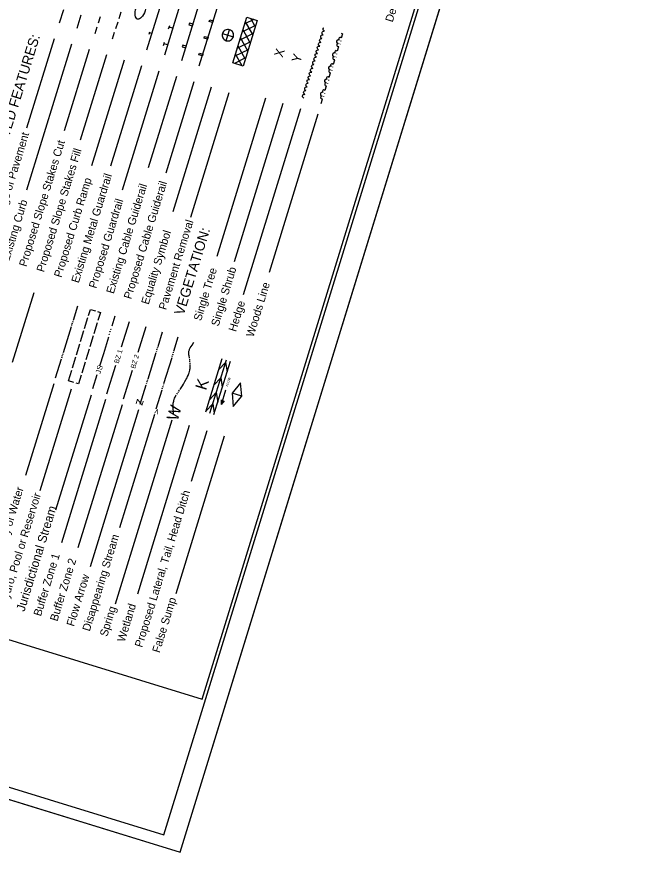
# Model space of a CAD drawing. Extents: x 1347947 to 1350662, y 1027710 to 1030532.
# Drawn here: x 1349987 to 1350662, y 1027875 to 1028788 of the extents above; entities that cross this region are included whole.
import ezdxf

# ---------------------------------------------------------------- set-up
doc = ezdxf.new("R2010")
doc.units = 0
doc.layers.add('Sheet Symbology CELL', color=7, linetype='Continuous')

msp = doc.modelspace()

# ---------------------------------------------------------------- linework, layer by layer
at = {"layer": 'Sheet Symbology CELL'}
for p, q in [((1350165.97, 1027874.54), (1350661.6, 1029483.96)), ((1350129.68, 1028751.93), (1350153.22, 1028828.39)), ((1350172.34, 1028822.5), (1350148.79, 1028746.04)), ((1350167.9, 1028740.16), (1350191.45, 1028816.61)), ((1350187.02, 1028734.27), (1350210.56, 1028810.73)), ((1350034.27, 1028781.48), (1350038.68, 1028795.81)), ((1350053.38, 1028775.59), (1350057.8, 1028789.93)), ((1350078.63, 1028788.01), (1350076.41, 1028780.79)), ((1350101.13, 1028793.11), (1350098.89, 1028785.85)), ((1350223.75, 1028737.56), (1350239.08, 1028787.35)), ((1350246.68, 1028785.01), (1350236.89, 1028780.23)), ((1350239.08, 1028787.35), (1350250.27, 1028783.91)), ((1350248.25, 1028777.36), (1350243.29, 1028786.05)), ((1350072.95, 1028769.56), (1350075.19, 1028776.83)), ((1350097.74, 1028782.12), (1350095.52, 1028774.91)), ((1350153.47, 1028774.66), (1350154.65, 1028778.48)), ((1350157.83, 1028775.41), (1350154.06, 1028776.57)), ((1350248.59, 1028778.46), (1350234.15, 1028771.34)), ((1350250.27, 1028783.91), (1350234.93, 1028734.11)), ((1350245.53, 1028768.52), (1350237.57, 1028782.43)), ((1350322.28, 1028774.44), (1350322.56, 1028775.35)), ((1350322.56, 1028775.35), (1350323.27, 1028775.97)), ((1350323.27, 1028775.97), (1350323.33, 1028776)), ((1350092.06, 1028763.68), (1350094.3, 1028770.94)), ((1350132.33, 1028769.04), (1350133.07, 1028771.43)), ((1350135.09, 1028769.5), (1350132.7, 1028770.24)), ((1350212.31, 1028769.62), (1350218.28, 1028767.78)), ((1350216.44, 1028761.81), (1350218.28, 1028767.78)), ((1350218.28, 1028767.78), (1350220.12, 1028773.75)), ((1350218.28, 1028767.78), (1350224.25, 1028765.94)), ((1350245.85, 1028769.57), (1350231.43, 1028762.5)), ((1350242.79, 1028759.63), (1350234.85, 1028773.59)), ((1350319.78, 1028766.32), (1350320.05, 1028767.23)), ((1350319.97, 1028765.42), (1350319.78, 1028766.32)), ((1350320.05, 1028767.23), (1350320.77, 1028767.84)), ((1350320.77, 1028767.84), (1350321.55, 1028768.18)), ((1350321.03, 1028770.38), (1350321.31, 1028771.29)), ((1350321.22, 1028769.48), (1350321.03, 1028770.38)), ((1350321.67, 1028768.72), (1350321.22, 1028769.48)), ((1350321.31, 1028771.29), (1350322.02, 1028771.91)), ((1350321.55, 1028768.18), (1350322.42, 1028768.12)), ((1350322.49, 1028768.15), (1350321.67, 1028768.72)), ((1350322.02, 1028771.91), (1350322.8, 1028772.24)), ((1350322.47, 1028773.55), (1350322.28, 1028774.44)), ((1350322.92, 1028772.78), (1350322.47, 1028773.55)), ((1350322.8, 1028772.24), (1350323.67, 1028772.18)), ((1350323.74, 1028772.21), (1350322.92, 1028772.78)), ((1350342.41, 1028764.89), (1350343.88, 1028769.67)), ((1350028.26, 1028763.94), (1349998.14, 1028666.12)), ((1350047.38, 1028758.05), (1349998.18, 1028598.3)), ((1350147.88, 1028756.5), (1350149.06, 1028760.32)), ((1350152.24, 1028757.25), (1350148.47, 1028758.41)), ((1350243.11, 1028760.68), (1350228.71, 1028753.66)), ((1350240.05, 1028750.74), (1350232.12, 1028764.75)), ((1350317.27, 1028758.2), (1350317.55, 1028759.1)), ((1350317.47, 1028757.3), (1350317.27, 1028758.2)), ((1350317.91, 1028756.53), (1350317.47, 1028757.3)), ((1350317.55, 1028759.1), (1350318.27, 1028759.72)), ((1350318.27, 1028759.72), (1350319.05, 1028760.05)), ((1350318.52, 1028762.26), (1350318.8, 1028763.16)), ((1350318.72, 1028761.36), (1350318.52, 1028762.26)), ((1350319.16, 1028760.6), (1350318.72, 1028761.36)), ((1350318.8, 1028763.16), (1350319.52, 1028763.78)), ((1350319.05, 1028760.05), (1350319.92, 1028760)), ((1350319.98, 1028760.03), (1350319.16, 1028760.6)), ((1350319.52, 1028763.78), (1350320.3, 1028764.12)), ((1350320.41, 1028764.66), (1350319.97, 1028765.42)), ((1350320.3, 1028764.12), (1350321.17, 1028764.06)), ((1350321.23, 1028764.09), (1350320.41, 1028764.66)), ((1350340.81, 1028758.01), (1350340.96, 1028758.49)), ((1350341.84, 1028761.35), (1350341.99, 1028761.83)), ((1350066.49, 1028752.16), (1350039.06, 1028663.1)), ((1350240.39, 1028751.84), (1350225.97, 1028744.77)), ((1350237.33, 1028741.9), (1350229.39, 1028755.86)), ((1350314.51, 1028747.54), (1350315.3, 1028747.87)), ((1350314.77, 1028750.07), (1350315.05, 1028750.98)), ((1350314.97, 1028749.17), (1350314.77, 1028750.07)), ((1350315.41, 1028748.41), (1350314.97, 1028749.17)), ((1350315.05, 1028750.98), (1350315.76, 1028751.6)), ((1350315.3, 1028747.87), (1350316.17, 1028747.81)), ((1350316.23, 1028747.84), (1350315.41, 1028748.41)), ((1350315.76, 1028751.6), (1350316.55, 1028751.93)), ((1350316.02, 1028754.13), (1350316.3, 1028755.04)), ((1350316.22, 1028753.24), (1350316.02, 1028754.13)), ((1350316.66, 1028752.47), (1350316.22, 1028753.24)), ((1350316.3, 1028755.04), (1350317.02, 1028755.66)), ((1350316.55, 1028751.93), (1350317.42, 1028751.87)), ((1350317.48, 1028751.91), (1350316.66, 1028752.47)), ((1350317.02, 1028755.66), (1350317.8, 1028755.99)), ((1350317.8, 1028755.99), (1350318.67, 1028755.93)), ((1350318.73, 1028755.97), (1350317.91, 1028756.53)), ((1350337.99, 1028750.56), (1350339.47, 1028755.34)), ((1350085.61, 1028746.28), (1350056.84, 1028652.87)), ((1350104.72, 1028740.39), (1350069.13, 1028624.82)), ((1350237.65, 1028742.95), (1350225.47, 1028737.03)), ((1350233.83, 1028734.45), (1350226.65, 1028746.97)), ((1350311.02, 1028737.89), (1350311.3, 1028738.79)), ((1350311.3, 1028738.79), (1350312.01, 1028739.41)), ((1350312.01, 1028739.41), (1350312.8, 1028739.75)), ((1350312.27, 1028741.95), (1350312.55, 1028742.86)), ((1350312.46, 1028741.05), (1350312.27, 1028741.95)), ((1350312.91, 1028740.29), (1350312.46, 1028741.05)), ((1350312.55, 1028742.86), (1350313.26, 1028743.47)), ((1350312.8, 1028739.75), (1350313.67, 1028739.69)), ((1350313.73, 1028739.72), (1350312.91, 1028740.29)), ((1350313.26, 1028743.47), (1350314.05, 1028743.81)), ((1350313.52, 1028746.01), (1350313.8, 1028746.92)), ((1350313.72, 1028745.11), (1350313.52, 1028746.01)), ((1350314.16, 1028744.35), (1350313.72, 1028745.11)), ((1350313.8, 1028746.92), (1350314.51, 1028747.54)), ((1350314.05, 1028743.81), (1350314.92, 1028743.75)), ((1350314.98, 1028743.78), (1350314.16, 1028744.35)), ((1350333.58, 1028736.22), (1350335.05, 1028741)), ((1350336.4, 1028743.67), (1350336.54, 1028744.15)), ((1350337.43, 1028747.02), (1350337.57, 1028747.5)), ((1350123.67, 1028734.39), (1350089.87, 1028624.64)), ((1350234.93, 1028734.11), (1350223.75, 1028737.56)), ((1350224.32, 1028737.38), (1350223.91, 1028738.08)), ((1350308.52, 1028729.76), (1350308.8, 1028730.67)), ((1350308.71, 1028728.87), (1350308.52, 1028729.76)), ((1350308.8, 1028730.67), (1350309.51, 1028731.29)), ((1350309.51, 1028731.29), (1350310.29, 1028731.62)), ((1350309.77, 1028733.82), (1350310.05, 1028734.73)), ((1350309.96, 1028732.93), (1350309.77, 1028733.82)), ((1350310.41, 1028732.16), (1350309.96, 1028732.93)), ((1350310.05, 1028734.73), (1350310.76, 1028735.35)), ((1350310.29, 1028731.62), (1350311.16, 1028731.56)), ((1350311.23, 1028731.6), (1350310.41, 1028732.16)), ((1350310.76, 1028735.35), (1350311.54, 1028735.68)), ((1350311.21, 1028736.99), (1350311.02, 1028737.89)), ((1350311.66, 1028736.22), (1350311.21, 1028736.99)), ((1350311.54, 1028735.68), (1350312.42, 1028735.63)), ((1350312.48, 1028735.66), (1350311.66, 1028736.22)), ((1350331.98, 1028729.34), (1350332.13, 1028729.82)), ((1350333.01, 1028732.68), (1350333.16, 1028733.16)), ((1350142.79, 1028728.5), (1350102.69, 1028598.3)), ((1350161.9, 1028722.62), (1350131.2, 1028622.94)), ((1350306.02, 1028721.64), (1350306.3, 1028722.55)), ((1350306.21, 1028720.74), (1350306.02, 1028721.64)), ((1350306.66, 1028719.98), (1350306.21, 1028720.74)), ((1350306.3, 1028722.55), (1350307.01, 1028723.16)), ((1350307.01, 1028723.16), (1350307.79, 1028723.5)), ((1350307.27, 1028725.7), (1350307.55, 1028726.61)), ((1350307.46, 1028724.8), (1350307.27, 1028725.7)), ((1350307.91, 1028724.04), (1350307.46, 1028724.8)), ((1350307.55, 1028726.61), (1350308.26, 1028727.23)), ((1350307.79, 1028723.5), (1350308.66, 1028723.44)), ((1350308.73, 1028723.47), (1350307.91, 1028724.04)), ((1350308.26, 1028727.23), (1350309.04, 1028727.56)), ((1350309.16, 1028728.1), (1350308.71, 1028728.87)), ((1350309.04, 1028727.56), (1350309.91, 1028727.5)), ((1350309.98, 1028727.53), (1350309.16, 1028728.1)), ((1350329.16, 1028721.89), (1350330.64, 1028726.67)), ((1350181.02, 1028716.73), (1350150.32, 1028617.05)), ((1350303.26, 1028710.98), (1350304.04, 1028711.31)), ((1350303.51, 1028713.52), (1350303.79, 1028714.42)), ((1350303.71, 1028712.62), (1350303.51, 1028713.52)), ((1350304.15, 1028711.85), (1350303.71, 1028712.62)), ((1350303.79, 1028714.42), (1350304.51, 1028715.04)), ((1350304.04, 1028711.31), (1350304.91, 1028711.25)), ((1350304.97, 1028711.29), (1350304.15, 1028711.85)), ((1350304.51, 1028715.04), (1350305.29, 1028715.38)), ((1350304.77, 1028717.58), (1350305.04, 1028718.49)), ((1350304.96, 1028716.68), (1350304.77, 1028717.58)), ((1350305.4, 1028715.92), (1350304.96, 1028716.68)), ((1350305.04, 1028718.49), (1350305.76, 1028719.1)), ((1350305.29, 1028715.38), (1350306.16, 1028715.32)), ((1350306.22, 1028715.35), (1350305.4, 1028715.92)), ((1350305.76, 1028719.1), (1350306.54, 1028719.44)), ((1350306.54, 1028719.44), (1350307.41, 1028719.38)), ((1350307.47, 1028719.41), (1350306.66, 1028719.98)), ((1350324.75, 1028707.55), (1350326.22, 1028712.33)), ((1350327.57, 1028715), (1350327.71, 1028715.48)), ((1350328.6, 1028718.35), (1350328.74, 1028718.83)), ((1350200.13, 1028710.85), (1350158.15, 1028574.54)), ((1350219.24, 1028704.96), (1350177.27, 1028568.65)), ((1350299.76, 1028701.33), (1350300.04, 1028702.24)), ((1350300.04, 1028702.24), (1350300.75, 1028702.86)), ((1350300.75, 1028702.86), (1350301.54, 1028703.19)), ((1350301.01, 1028705.39), (1350301.29, 1028706.3)), ((1350301.21, 1028704.5), (1350301.01, 1028705.39)), ((1350301.65, 1028703.73), (1350301.21, 1028704.5)), ((1350301.29, 1028706.3), (1350302.01, 1028706.92)), ((1350301.54, 1028703.19), (1350302.41, 1028703.13)), ((1350302.47, 1028703.16), (1350301.65, 1028703.73)), ((1350302.01, 1028706.92), (1350302.79, 1028707.25)), ((1350302.26, 1028709.45), (1350302.54, 1028710.36)), ((1350302.46, 1028708.56), (1350302.26, 1028709.45)), ((1350302.9, 1028707.79), (1350302.46, 1028708.56)), ((1350302.54, 1028710.36), (1350303.26, 1028710.98)), ((1350302.79, 1028707.25), (1350303.66, 1028707.19)), ((1350303.72, 1028707.23), (1350302.9, 1028707.79)), ((1350324.18, 1028704.01), (1350324.33, 1028704.49)), ((1350259.35, 1028699.03), (1350206.04, 1028525.93)), ((1350278.46, 1028693.15), (1350225.15, 1028520.04)), ((1350299.96, 1028700.43), (1350299.76, 1028701.33)), ((1350300.4, 1028699.67), (1350299.96, 1028700.43)), ((1350301.22, 1028699.1), (1350300.4, 1028699.67)), ((1350320.33, 1028693.22), (1350321.81, 1028697.99)), ((1350323.15, 1028700.67), (1350323.3, 1028701.14)), ((1350297.57, 1028687.26), (1350234.98, 1028483.99)), ((1350316.69, 1028681.37), (1350263.38, 1028508.27)), ((1349982.76, 1028410.18), (1350006.3, 1028486.64)), ((1350049.24, 1028456.18), (1350054.09, 1028471.92)), ((1350061.56, 1028447.19), (1350065.24, 1028459.13)), ((1350038.35, 1028420.81), (1350047.18, 1028449.49)), ((1350047.47, 1028450.44), (1350047.77, 1028451.4)), ((1350048.06, 1028452.35), (1350048.36, 1028453.31)), ((1350048.65, 1028454.26), (1350048.94, 1028455.22)), ((1350075.32, 1028453.39), (1350071.64, 1028441.44)), ((1350110.26, 1028454.62), (1350101.64, 1028426.61)), ((1350128.4, 1028449.04), (1350119.78, 1028421.03)), ((1350057.15, 1028432.85), (1350060.83, 1028444.8)), ((1350070.91, 1028439.05), (1350067.23, 1028427.11)), ((1350141.9, 1028427.64), (1350146.75, 1028443.39)), ((1350159.21, 1028422.31), (1350164.06, 1028438.05)), ((1350052.73, 1028418.52), (1350056.41, 1028430.46)), ((1350037.76, 1028418.9), (1350038.05, 1028419.86)), ((1350066.49, 1028424.72), (1350062.81, 1028412.77)), ((1350131.01, 1028392.28), (1350139.84, 1028420.95)), ((1350140.13, 1028421.91), (1350140.43, 1028422.86)), ((1350140.72, 1028423.82), (1350141.01, 1028424.77)), ((1350141.31, 1028425.73), (1350141.6, 1028426.69)), ((1350158.04, 1028418.49), (1350158.33, 1028419.44)), ((1350158.62, 1028420.4), (1350158.92, 1028421.35)), ((1350029.81, 1028393.08), (1350036.29, 1028414.12)), ((1350036.58, 1028415.08), (1350036.88, 1028416.04)), ((1350037.17, 1028416.99), (1350037.47, 1028417.95)), ((1350048.32, 1028404.18), (1350052, 1028416.13)), ((1350062.08, 1028410.38), (1350058.4, 1028398.43)), ((1350148.32, 1028386.95), (1350157.15, 1028415.62)), ((1350157.45, 1028416.57), (1350157.74, 1028417.53)), ((1350176.8, 1028410.67), (1350176.7, 1028411.65)), ((1350194.01, 1028356.08), (1350211.97, 1028414.39)), ((1350198.52, 1028354.42), (1350216.56, 1028412.98)), ((1350203.04, 1028353.3), (1350221, 1028411.61)), ((1350208.23, 1028402.24), (1350215.64, 1028410.01)), ((1350215.64, 1028410.01), (1350217.34, 1028399.71)), ((1350043.9, 1028389.85), (1350047.58, 1028401.79)), ((1350085.98, 1028375.78), (1350095.63, 1028407.12)), ((1350104.12, 1028370.19), (1350113.77, 1028401.53)), ((1350176.96, 1028408.67), (1350176.87, 1028409.66)), ((1350203.01, 1028385.29), (1350210.49, 1028393.27)), ((1350210.49, 1028393.27), (1350212.14, 1028382.85)), ((1350027.89, 1028386.85), (1349996.99, 1028286.5)), ((1350049.93, 1028387.99), (1350043.9, 1028389.85)), ((1350122.47, 1028364.54), (1350128.95, 1028385.59)), ((1350129.24, 1028386.55), (1350129.54, 1028387.5)), ((1350129.83, 1028388.46), (1350130.12, 1028389.41)), ((1350130.42, 1028390.37), (1350130.71, 1028391.32)), ((1350147.15, 1028383.12), (1350147.44, 1028384.08)), ((1350147.73, 1028385.04), (1350148.03, 1028385.99)), ((1350232.15, 1028387.63), (1350222.95, 1028376.53)), ((1350233.51, 1028373.28), (1350232.15, 1028387.63)), ((1350047, 1028380.97), (1350012.75, 1028269.73)), ((1350068.6, 1028374.31), (1350029.87, 1028248.54)), ((1350139.78, 1028359.21), (1350146.26, 1028380.26)), ((1350146.56, 1028381.21), (1350146.85, 1028382.17)), ((1350164.69, 1028378.76), (1350165.28, 1028379.57)), ((1350198.02, 1028369.09), (1350205.49, 1028377.03)), ((1350205.49, 1028377.03), (1350207.14, 1028366.61)), ((1350211.1, 1028364.16), (1350216, 1028380.08)), ((1350233.51, 1028373.28), (1350222.95, 1028376.53)), ((1350222.95, 1028376.53), (1350224, 1028362.01)), ((1350224, 1028362.01), (1350233.51, 1028373.28)), ((1350084.48, 1028369.42), (1350036.28, 1028212.92)), ((1350194.28, 1028356.94), (1350201.75, 1028364.88)), ((1350201.75, 1028364.88), (1350203.39, 1028354.42)), ((1350211.1, 1028364.16), (1350211.22, 1028369.15)), ((1350211.1, 1028364.16), (1350214.37, 1028368.18)), ((1350102.51, 1028363.87), (1350054.32, 1028207.37)), ((1350120.55, 1028358.32), (1350067.62, 1028186.44)), ((1350156.98, 1028347.1), (1350095.03, 1028145.95)), ((1350137.86, 1028352.98), (1350099.75, 1028229.21)), ((1350176.09, 1028341.21), (1350119.23, 1028156.56)), ((1350214.32, 1028329.44), (1350161.26, 1028157.15)), ((1350195.21, 1028335.33), (1350178.08, 1028279.73)), ((1349114.69, 1028198.29), (1350165.97, 1027874.54))]:
    msp.add_line(p, q, dxfattribs=at)
for points in [[(1350165.97, 1027874.54), (1350661.6, 1029483.96), (1349610.32, 1029807.71), (1349114.69, 1028198.29)], [(1350148.34, 1027893.58), (1350638.82, 1029486.26), (1349630.46, 1029796.8), (1349139.98, 1028204.11)], [(1349629.21, 1029784.1), (1349187.74, 1028350.54), (1350190.26, 1028041.81), (1350631.74, 1029475.37)], [(1350197.75, 1028782.72), (1350198.34, 1028784.63), (1350202.17, 1028783.45), (1350201.58, 1028781.54)], [(1350179.52, 1028777.88), (1350180.11, 1028779.8), (1350176.29, 1028780.97), (1350175.7, 1028779.06)], [(1350192.16, 1028764.56), (1350192.75, 1028766.47), (1350196.57, 1028765.3), (1350195.98, 1028763.38)], [(1350172.17, 1028753.99), (1350172.75, 1028755.9), (1350168.93, 1028757.08), (1350168.34, 1028755.17)], [(1350186.57, 1028746.4), (1350187.16, 1028748.32), (1350190.98, 1028747.14), (1350190.39, 1028745.23)]]:
    msp.add_lwpolyline(points, close=True, dxfattribs=at)
for points in [[(1350065.98, 1028461.52), (1350067.99, 1028468.05), (1350073.41, 1028466.38)], [(1350075.8, 1028465.64), (1350078.81, 1028464.71), (1350076.06, 1028455.78)], [(1350091.73, 1028450.1), (1350095.09, 1028461.01)], [(1350082.43, 1028419.91), (1350088.02, 1028438.06)], [(1350176.31, 1028414.64), (1350176.22, 1028415.16), (1350175.82, 1028417.34), (1350175.65, 1028418.44), (1350175.55, 1028419.55), (1350175.53, 1028420.38), (1350175.57, 1028421.1), (1350175.63, 1028421.74), (1350175.71, 1028422.29), (1350175.94, 1028423.24), (1350176.15, 1028423.93), (1350176.35, 1028424.43), (1350176.69, 1028425.17), (1350177.09, 1028425.87), (1350179.07, 1028428.97), (1350181.05, 1028432.06)], [(1350078.31, 1028406.5), (1350082.43, 1028419.91)], [(1350176.6, 1028412.65), (1350176.58, 1028412.87), (1350176.48, 1028413.64)], [(1350165.87, 1028380.38), (1350166.34, 1028381.03), (1350167.15, 1028382.25), (1350168.62, 1028384.61), (1350169.71, 1028386.39), (1350171.27, 1028389.09), (1350172.78, 1028391.83), (1350173.57, 1028393.36), (1350174.22, 1028394.73), (1350174.76, 1028395.95), (1350175.19, 1028397.04), (1350175.54, 1028397.99), (1350175.83, 1028398.84), (1350176.26, 1028400.33), (1350176.53, 1028401.46), (1350176.69, 1028402.33), (1350176.89, 1028403.61), (1350177.01, 1028404.91), (1350177.04, 1028405.91), (1350177.05, 1028406.78), (1350177.01, 1028407.67)], [(1350057.66, 1028396.05), (1350054.73, 1028386.51), (1350052.31, 1028387.26)], [(1350070.64, 1028381.61), (1350075.35, 1028396.91)], [(1350158.9, 1028353.33), (1350158.6, 1028356.4), (1350158.29, 1028359.47), (1350158.24, 1028360.23), (1350158.19, 1028361.57), (1350158.23, 1028362.58), (1350158.33, 1028364.08), (1350158.52, 1028365.56), (1350158.74, 1028366.79), (1350158.98, 1028367.87), (1350159.24, 1028368.79), (1350159.49, 1028369.61), (1350160.01, 1028371), (1350160.44, 1028372.03), (1350160.81, 1028372.78), (1350161.4, 1028373.9), (1350161.84, 1028374.65)], [(1350162.38, 1028375.5), (1350162.64, 1028375.91), (1350162.93, 1028376.33)], [(1350163.51, 1028377.14), (1350163.76, 1028377.5), (1350164.1, 1028377.96)]]:
    msp.add_lwpolyline(points, dxfattribs=at)
for centre, radius, start, end in [((1350218.28, 1028767.78), 6.25, 162.8778, 252.88234), ((1350218.28, 1028767.78), 6.25, 72.8778, 162.88234), ((1350218.28, 1028767.78), 6.25, 342.8778, 72.88234), ((1350343.34, 1028771.35), 1.58, 229.13443, 276.6324), ((1350218.28, 1028767.78), 6.25, 252.8778, 342.88234), ((1350339, 1028760.66), 2.06, 58.84717, 266.91966), ((1350338.92, 1028757.02), 1.58, 91.31837, 292.11494), ((1350340.98, 1028763.71), 1.58, 33.6519, 234.44847), ((1350334.58, 1028746.32), 2.06, 58.84717, 266.91966), ((1350336.57, 1028749.37), 1.58, 33.6519, 234.44847), ((1350334.51, 1028742.68), 1.58, 91.31837, 292.11494), ((1350330.17, 1028731.99), 2.06, 58.84717, 266.91966), ((1350330.09, 1028728.35), 1.58, 91.31837, 292.11494), ((1350332.15, 1028735.04), 1.58, 33.6519, 234.44847), ((1350327.74, 1028720.7), 1.58, 33.6519, 234.44847), ((1350325.75, 1028717.65), 2.06, 58.84717, 266.91966), ((1350325.68, 1028714.01), 1.58, 91.31837, 292.11494), ((1350321.34, 1028703.32), 2.06, 58.84717, 266.91966), ((1350323.32, 1028706.37), 1.58, 33.6519, 234.44847), ((1350321.26, 1028699.68), 1.58, 91.31837, 292.11494)]:
    msp.add_arc(centre, radius, start, end, dxfattribs=at)
for centre, major_axis, ratio in [((1350122.76, 1028796.04), (3.3, 10.72), 0.462467), ((1350090.25, 1028446.25), (-0.188, 0.058), 0.938496), ((1350088.62, 1028440.95), (-0.188, 0.058), 0.938496), ((1350089.49, 1028443.78), (-0.188, 0.058), 0.938496)]:
    msp.add_ellipse(centre, major_axis=major_axis, ratio=ratio, dxfattribs=at)

# ---------------------------------------------------------------- texts
for s, height, rotation, p in [('Designated U/G Fiber Optics Cable (S.U.E.*)', 8.75, 72.88342, (1350398.39, 1028781.41)), ('ROADS AND RELATED FEATURES:', 11, 72.88342, (1349940.58, 1028531.71)), ('X', 10, 72.88342, (1350278.07, 1028742.85)), ('Y', 10, 72.88342, (1350297.19, 1028736.97)), ('Existing Edge of Pavement', 8.75, 72.88342, (1349959.69, 1028525.82)), ('Proposed Slope Stakes Cut', 8.75, 72.88342, (1349997.92, 1028514.05)), ('Proposed Slope Stakes Fill', 8.75, 72.88342, (1350017.04, 1028508.16)), ('Proposed Curb Ramp', 8.75, 72.88342, (1350036.15, 1028502.28)), ('Existing Metal Guardrail', 8.75, 72.88342, (1350055.1, 1028496.27)), ('Existing Cable Guiderail', 8.75, 72.88342, (1350093.32, 1028484.52)), ('Proposed Cable Guiderail', 8.75, 72.88342, (1350112.44, 1028478.63)), ('Existing Curb', 8.75, 72.88342, (1349978.81, 1028519.93)), ('Proposed Guardrail', 8.75, 72.88342, (1350074.21, 1028490.4)), ('Pavement Removal', 8.75, 72.88342, (1350150.67, 1028466.86)), ('VEGETATION:', 11, 72.88342, (1350169.86, 1028460.94)), ('Equality Symbol', 8.75, 72.88342, (1350131.55, 1028472.75)), ('Single Tree', 8.75, 72.88342, (1350188.87, 1028454.79)), ('Single Shrub', 8.75, 72.88342, (1350207.98, 1028448.91)), ('Woods Line', 8.75, 72.88342, (1350246.21, 1028437.14)), ('Hedge', 8.75, 72.88342, (1350227.09, 1028443.02)), ('BZ 1', 5.315, 72.88342, (1350098.66, 1028408.43)), ('BZ 2', 5.315, 72.88342, (1350116.73, 1028402.87)), ('JS', 5.906, 72.88342, (1350078.86, 1028396.99)), ('K', 12.75, 72.88342, (1350194.37, 1028378.9)), ('FLOW', 2.593, 72.88342, (1350218.45, 1028383.44)), ('z', 10, 252.88344, (1350119.16, 1028370.8)), ('W', 12.75, 72.88342, (1350163.11, 1028345.36)), ('v', 6.6, 162.64256, (1350143.35, 1028358.11)), ('Stream or Body of Water', 8.75, 72.88342, (1349957.14, 1028149.42)), ('Hydro, Pool or Reservoir', 8.75, 72.88342, (1349976.25, 1028143.53)), ('Proposed Lateral, Tail, Head Ditch', 8.75, 72.88342, (1350124.45, 1028097.89)), ('Jurisdictional Stream', 9.646, 72.88342, (1349995.78, 1028137.17)), ('Disappearing Stream', 8.75, 72.88342, (1350067.11, 1028115.55)), ('Buffer Zone 1', 8.75, 72.88342, (1350013.73, 1028131.99)), ('Buffer Zone 2', 8.75, 72.88342, (1350031.76, 1028126.44)), ('Flow Arrow', 8.75, 72.88342, (1350049.8, 1028120.89)), ('Wetland', 8.75, 72.88342, (1350105.34, 1028103.78)), ('False Sump', 8.75, 72.88342, (1350143.57, 1028092.01)), ('Spring', 8.75, 72.88342, (1350086.23, 1028109.67))]:
    msp.add_text(s, height=height, rotation=rotation, dxfattribs=at).set_placement(p)

doc.saveas('drawing.dxf')
